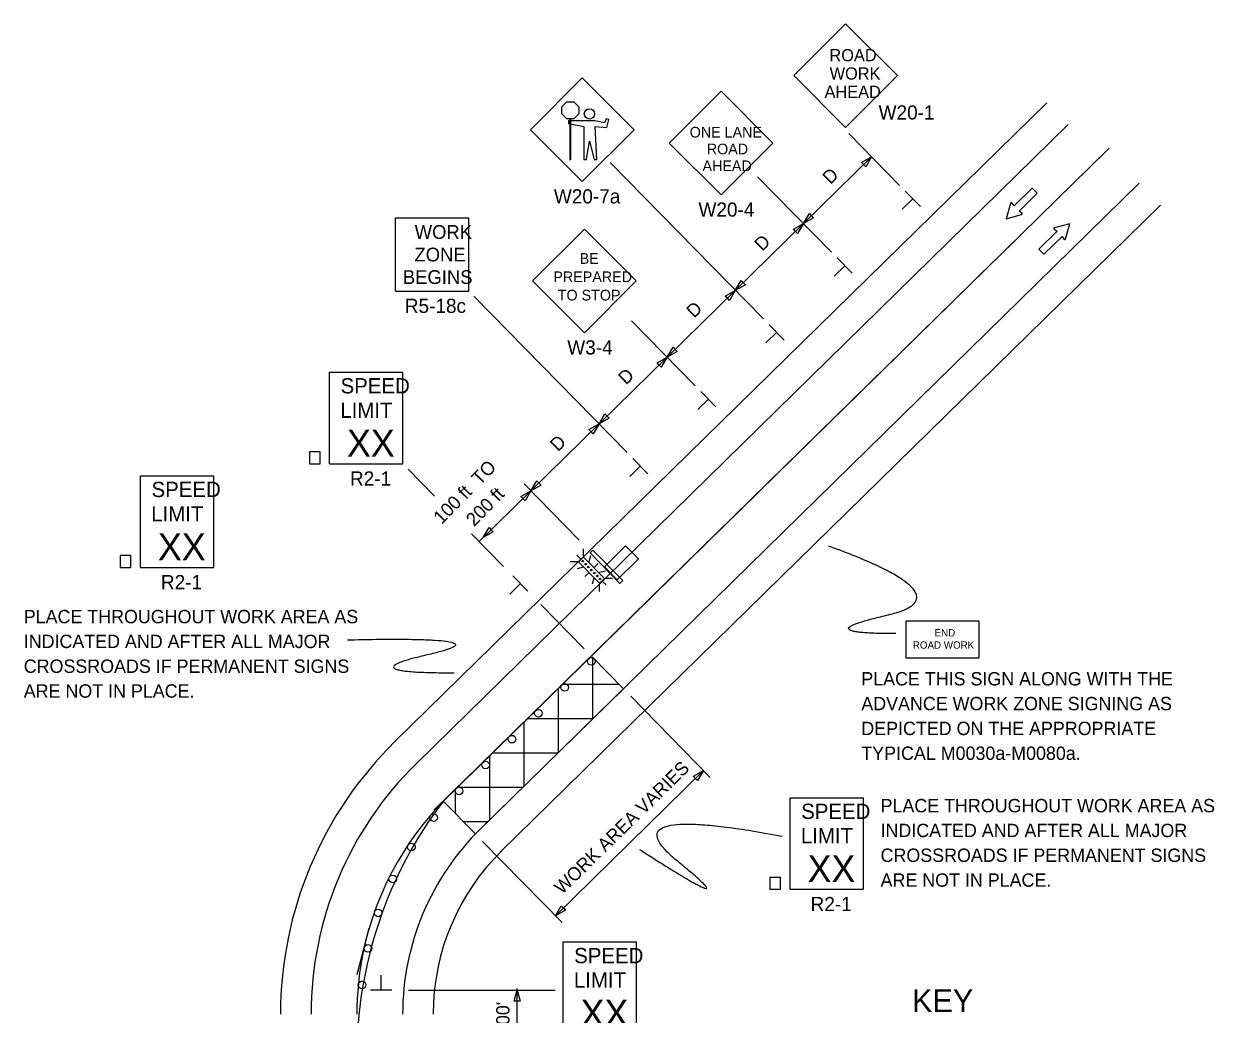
# Model space of a CAD drawing. Extents: x 16738 to 18485, y 7217 to 8213.
# Drawn here: x 16779 to 17403, y 7694 to 8213 of the extents above; entities that cross this region are included whole.
import ezdxf

# ---------------------------------------------------------------- set-up
doc = ezdxf.new("R2010")
doc.units = 0
for name, color, linetype in [('ALI_LEGAL_EX', 7, 'Continuous'), ('MT_SCRATCH_LEVEL_E', 7, 'Continuous'), ('PAVT_EDGE_EX', 7, 'Continuous'), ('TRAFFIC_SIGNS_PR', 7, 'Continuous'), ('TYPICAL_TEXT_DIMEN_EX', 7, 'Continuous'), ('TYPICAL_TEXT_DIMEN_PR', 7, 'Continuous')]:
    doc.layers.add(name, color=color, linetype=linetype)

msp = doc.modelspace()

# ---------------------------------------------------------------- linework, layer by layer
at = {"layer": 'ALI_LEGAL_EX'}
msp.add_line((16999.12, 7805.61), (17348.33, 8147.9), dxfattribs=at)
msp.add_arc((17174.73, 7671.79), 220.78, 142.68987, 180.19827, dxfattribs=at)
at = {"layer": 'MT_SCRATCH_LEVEL_E'}
for p, q in [((17307.86, 8126.93), (17298.39, 8117.65)), ((17307.86, 8126.93), (17298.39, 8117.65)), ((17301.01, 8114.98), (17310.48, 8124.26)), ((17301.01, 8114.98), (17310.48, 8124.26)), ((17310.48, 8124.26), (17307.86, 8126.93)), ((17310.48, 8124.26), (17307.86, 8126.93)), ((17296.55, 8119), (17294.28, 8110.97)), ((17296.55, 8119), (17294.28, 8110.97)), ((17298.39, 8117.65), (17297.37, 8119.14)), ((17298.39, 8117.65), (17297.37, 8119.14)), ((17294.28, 8110.97), (17302.33, 8113.11)), ((17294.28, 8110.97), (17302.33, 8113.11)), ((17302.48, 8113.93), (17301.01, 8114.98)), ((17302.48, 8113.93), (17301.01, 8114.98)), ((17320.93, 8104.35), (17311.46, 8095.07)), ((17320.93, 8104.35), (17311.46, 8095.07)), ((17319.46, 8105.4), (17320.93, 8104.35)), ((17319.46, 8105.4), (17320.93, 8104.35)), ((17327.66, 8108.35), (17319.61, 8106.22)), ((17327.66, 8108.35), (17319.61, 8106.22)), ((17325.39, 8100.32), (17327.66, 8108.35)), ((17325.39, 8100.32), (17327.66, 8108.35)), ((17314.08, 8092.4), (17323.55, 8101.68)), ((17314.08, 8092.4), (17323.55, 8101.68)), ((17323.55, 8101.68), (17324.56, 8100.19)), ((17323.55, 8101.68), (17324.56, 8100.19)), ((17311.46, 8095.07), (17314.08, 8092.4)), ((17311.46, 8095.07), (17314.08, 8092.4))]:
    msp.add_line(p, q, dxfattribs=at)
for centre, start, end in [((17296.99, 8118.87), 34.46189, 164.19881), ((17296.99, 8118.87), 34.46189, 164.19881), ((17302.2, 8113.55), 284.85054, 54.38951), ((17302.2, 8113.55), 284.85054, 54.38951), ((17319.73, 8105.77), 104.85054, 234.38951), ((17319.73, 8105.77), 104.85054, 234.38951), ((17324.94, 8100.46), 214.46189, 344.19881), ((17324.94, 8100.46), 214.46189, 344.19881)]:
    msp.add_arc(centre, 0.463, start, end, dxfattribs=at)
at = {"layer": 'PAVT_EDGE_EX'}
for p, q in [((16973.95, 7836.95), (17315.52, 8171.75)), ((17326.72, 8160.32), (16985.15, 7825.53)), ((17000.42, 7806.89), (17347.09, 8146.68)), ((17363.89, 8129.54), (17017.22, 7789.74)), ((17375.09, 8118.11), (17029.31, 7779.19)), ((17077.23, 7881.37), (17093.63, 7864.64)), ((17076.79, 7878.94), (17076.79, 7878.94))]:
    msp.add_line(p, q, dxfattribs=at)
for points in [[(17280.01, 8080.93), (17297.86, 8098.43)], [(17208.6, 8010.93), (17226.45, 8028.43)], [(17137.18, 7940.93), (17155.03, 7958.43)], [(17065.76, 7870.94), (17083.62, 7888.43)], [(16994.35, 7800.94), (17012.2, 7818.44)], [(16954.21, 7715), (16960.41, 7739.22)]]:
    msp.add_lwpolyline(points, dxfattribs=at)
for centre, radius, start, end in [((17113.95, 7694.12), 200, 134.42581, 180), ((17113.95, 7694.12), 184, 134.42582, 180), ((17113.95, 7694.12), 160, 134.35623, 180), ((17113.95, 7694.12), 136, 134.35623, 180), ((17113.95, 7694.12), 120, 134.35623, 180), ((17155.85, 7650.09), 180.78, 134.42580555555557, 134.42580833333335), ((17155.85, 7650.09), 180.78, 134.42580555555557, 134.42580833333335), ((17155.85, 7650.09), 180.78, 134.42580555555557, 134.42580833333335), ((17155.85, 7650.09), 180.78, 134.42580555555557, 134.42580833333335)]:
    msp.add_arc(centre, radius, start, end, dxfattribs=at)
at = {"layer": 'TRAFFIC_SIGNS_PR'}
for p, q in [((17210.11, 8213.07), (17182.96, 8185.92)), ((17237.26, 8185.92), (17210.11, 8213.07)), ((17182.96, 8185.92), (17210.11, 8158.77)), ((17210.11, 8158.77), (17237.26, 8185.92)), ((17072.08, 8184.69), (17044.93, 8157.54)), ((17099.23, 8157.54), (17072.08, 8184.69)), ((17144.83, 8177.77), (17117.67, 8150.61)), ((17171.98, 8150.61), (17144.83, 8177.77)), ((17044.93, 8157.54), (17072.08, 8130.39)), ((17072.08, 8130.39), (17099.23, 8157.54)), ((17117.67, 8150.61), (17144.83, 8123.46)), ((17144.83, 8123.46), (17171.98, 8150.61)), ((16974.29, 8073), (16974.29, 8111.4)), ((16974.29, 8111.4), (17012.69, 8111.4)), ((17012.69, 8073), (17012.69, 8111.4)), ((17073.24, 8105.53), (17046.09, 8078.38)), ((17100.39, 8078.38), (17073.24, 8105.53)), ((17046.09, 8078.38), (17073.24, 8051.23)), ((17073.24, 8051.23), (17100.39, 8078.38)), ((16974.29, 8073), (17012.69, 8073)), ((16939.67, 8030.54), (16978.07, 8030.54)), ((16939.67, 7982.54), (16939.67, 8030.54)), ((16978.07, 7982.54), (16978.07, 8030.54)), ((16939.67, 7982.54), (16978.07, 7982.54)), ((16840.6, 7976.23), (16879, 7976.23)), ((16840.6, 7928.23), (16840.6, 7976.23)), ((16879, 7928.23), (16879, 7976.23)), ((17072.73, 7934), (17072.77, 7937.99)), ((17083.69, 7928.6), (17094.84, 7939.52)), ((17101.55, 7932.68), (17094.84, 7939.52)), ((17069.82, 7931.16), (17065.83, 7931.2)), ((17071.28, 7932.58), (17069.3, 7934.59)), ((17072.32, 7931.51), (17072.32, 7931.51)), ((17073.84, 7929.96), (17073.84, 7929.96)), ((17076.35, 7934.33), (17075.47, 7931.2)), ((17078.39, 7928.23), (17080.4, 7930.2)), ((17090.41, 7921.75), (17101.55, 7932.68)), ((16840.6, 7928.23), (16879, 7928.23)), ((17072.59, 7928.34), (17069.44, 7927.52)), ((17075.48, 7925.38), (17073.47, 7923.41)), ((17075.36, 7928.41), (17075.36, 7928.41)), ((17076.88, 7926.86), (17076.88, 7926.86)), ((17078.4, 7925.3), (17078.4, 7925.3)), ((17079.93, 7923.75), (17079.93, 7923.75)), ((17084.23, 7926.3), (17081.08, 7925.48)), ((17078.15, 7922.66), (17077.28, 7919.52)), ((17081.1, 7915.62), (17081.14, 7919.61)), ((17081.45, 7922.2), (17081.45, 7922.2)), ((17082.59, 7921.03), (17084.57, 7919.02)), ((17088.03, 7922.41), (17084.05, 7922.45)), ((17181.08, 7807.56), (17219.48, 7807.56)), ((17181.08, 7759.56), (17181.08, 7807.56)), ((17219.48, 7759.56), (17219.48, 7807.56)), ((17181.08, 7759.56), (17219.48, 7759.56)), ((17062.1, 7731.95), (17100.5, 7731.95)), ((17062.1, 7683.95), (17062.1, 7731.95)), ((17100.5, 7683.95), (17100.5, 7731.95))]:
    msp.add_line(p, q, dxfattribs=at)
for points in [[(17064.04, 8172.17), (17067.71, 8172.17), (17070.31, 8169.57), (17070.31, 8165.9), (17067.71, 8163.3), (17064.04, 8163.3), (17061.44, 8165.9), (17061.44, 8169.57)], [(17078.76, 8162.26), (17064.94, 8162.26), (17064.94, 8160.76), (17072.9, 8159.31), (17072.9, 8141.9), (17074.4, 8141.9), (17075.9, 8151.51), (17078.3, 8141.9), (17079.8, 8141.9), (17078.9, 8159.31), (17084.9, 8158.7), (17086.1, 8162.9), (17084.65, 8163.27), (17083.75, 8161.17)], [(17065.58, 8163.3), (17065.58, 8141.92), (17066.17, 8141.92), (17066.17, 8163.3)], [(16929.06, 7982.54), (16934.65, 7982.54), (16934.65, 7988.71), (16929.06, 7988.71)], [(17076.17, 7935.8), (17091.84, 7919.82), (17093.34, 7921.29), (17077.67, 7937.27)], [(17090.41, 7921.75), (17083.69, 7928.6), (17094.84, 7939.52), (17101.55, 7932.68)], [(16829.99, 7928.23), (16835.58, 7928.23), (16835.58, 7934.41), (16829.99, 7934.41)], [(17072.72, 7933.67), (17083.72, 7922.46), (17081.15, 7919.94), (17070.15, 7931.15)], [(17241.75, 7880.91), (17280.15, 7880.91), (17280.15, 7900.11), (17241.75, 7900.11)], [(17170.47, 7759.56), (17176.06, 7759.56), (17176.06, 7765.73), (17170.47, 7765.73)]]:
    msp.add_lwpolyline(points, close=True, dxfattribs=at)
for centre, radius in [((17075.88, 8165.88), 2.7), ((17072.32, 7931.51), 0.379), ((17073.84, 7929.96), 0.379), ((17075.36, 7928.41), 0.379), ((17076.88, 7926.86), 0.379), ((17078.4, 7925.3), 0.379), ((17079.93, 7923.75), 0.379), ((17081.43, 7922.21), 0.379), ((17076.79, 7878.94), 2), ((17062.95, 7865.37), 2), ((17049.1, 7851.8), 2), ((17035.26, 7838.23), 2), ((17021.42, 7824.66), 2), ((17007.57, 7811.09), 2), ((16994.18, 7797.16), 2), ((16982.47, 7781.73), 2), ((16972.74, 7764.98), 2), ((16965.13, 7747.17), 2), ((16959.75, 7728.56), 2), ((16956.7, 7709.43), 2)]:
    msp.add_circle(centre, radius, dxfattribs=at)
for points in [[(17236.53, 7893.52), (17189.3, 7893.52), (17274.32, 7912.87), (17201.2, 7939.42)], [(16949.14, 7890.29), (17034.03, 7892.22), (16949.01, 7872.87), (17004.89, 7873.04)], [(17102.14, 7780.44), (17160.35, 7743.05), (17084.36, 7804.9), (17176.81, 7787.41)]]:
    msp.add_open_spline(points, degree=2, dxfattribs=at)
at = {"layer": 'TYPICAL_TEXT_DIMEN_PR'}
for p, q in [((17238.44, 8128.39), (17211.76, 8155.61)), ((17223.74, 8143.39), (17188.03, 8108.39)), ((17218.45, 8140.41), (17223.74, 8143.39)), ((17218.45, 8140.41), (17223.74, 8143.39)), ((17223.74, 8143.39), (17220.65, 8138.17)), ((17223.74, 8143.39), (17220.65, 8138.17)), ((17167.02, 8058.4), (17086.68, 8140.37)), ((17219.55, 8139.29), (17218.45, 8140.41)), ((17219.55, 8139.29), (17218.45, 8140.41)), ((17220.65, 8138.17), (17219.55, 8139.29)), ((17220.65, 8138.17), (17219.55, 8139.29)), ((17202.73, 8093.39), (17163.97, 8132.94)), ((17241.41, 8125.36), (17249.29, 8117.32)), ((17245.35, 8121.34), (17239.79, 8115.89)), ((17188.03, 8108.39), (17191.12, 8113.62)), ((17188.03, 8108.39), (17191.12, 8113.62)), ((17193.31, 8111.38), (17188.03, 8108.39)), ((17193.31, 8111.38), (17188.03, 8108.39)), ((17191.12, 8113.62), (17192.22, 8112.5)), ((17191.12, 8113.62), (17192.22, 8112.5)), ((17192.22, 8112.5), (17193.31, 8111.38)), ((17192.22, 8112.5), (17193.31, 8111.38)), ((17188.03, 8108.39), (17152.32, 8073.4)), ((17182.74, 8105.41), (17188.03, 8108.39)), ((17182.74, 8105.41), (17188.03, 8108.39)), ((17183.84, 8104.29), (17182.74, 8105.41)), ((17183.84, 8104.29), (17182.74, 8105.41)), ((17184.94, 8103.17), (17183.84, 8104.29)), ((17184.94, 8103.17), (17183.84, 8104.29)), ((17188.03, 8108.39), (17184.94, 8103.17)), ((17188.03, 8108.39), (17184.94, 8103.17)), ((17209.64, 8086.34), (17204.08, 8080.89)), ((17205.7, 8090.36), (17213.58, 8082.33)), ((17152.32, 8073.4), (17116.61, 8038.4)), ((17147.04, 8070.41), (17152.32, 8073.4)), ((17147.04, 8070.41), (17152.32, 8073.4)), ((17152.32, 8073.4), (17149.24, 8068.17)), ((17152.32, 8073.4), (17149.24, 8068.17)), ((17152.32, 8073.4), (17155.41, 8078.62)), ((17157.61, 8076.38), (17152.32, 8073.4)), ((17155.41, 8078.62), (17156.51, 8077.5)), ((17156.51, 8077.5), (17157.61, 8076.38)), ((17095.61, 7988.39), (17015.31, 8070.33)), ((17148.14, 8069.29), (17147.04, 8070.41)), ((17148.14, 8069.29), (17147.04, 8070.41)), ((17149.24, 8068.17), (17148.14, 8069.29)), ((17149.24, 8068.17), (17148.14, 8069.29)), ((17131.32, 8023.39), (17097.95, 8057.44)), ((17170, 8055.36), (17177.87, 8047.33)), ((17173.93, 8051.35), (17168.37, 8045.9)), ((17116.61, 8038.4), (17119.7, 8043.62)), ((17116.61, 8038.4), (17119.7, 8043.62)), ((17119.7, 8043.62), (17120.8, 8042.5)), ((17119.7, 8043.62), (17120.8, 8042.5)), ((17120.8, 8042.5), (17121.9, 8041.38)), ((17120.8, 8042.5), (17121.9, 8041.38)), ((17116.62, 8038.39), (17080.91, 8003.39)), ((17111.33, 8035.41), (17116.62, 8038.39)), ((17111.33, 8035.41), (17116.62, 8038.39)), ((17116.62, 8038.39), (17113.53, 8033.17)), ((17116.62, 8038.39), (17113.53, 8033.17)), ((17121.9, 8041.38), (17116.61, 8038.4)), ((17121.9, 8041.38), (17116.61, 8038.4)), ((17112.43, 8034.29), (17111.33, 8035.41)), ((17112.43, 8034.29), (17111.33, 8035.41)), ((17113.53, 8033.17), (17112.43, 8034.29)), ((17113.53, 8033.17), (17112.43, 8034.29)), ((17134.29, 8020.36), (17142.16, 8012.33)), ((17138.23, 8016.35), (17132.67, 8010.9)), ((17080.91, 8003.4), (17083.99, 8008.62)), ((17080.91, 8003.4), (17083.99, 8008.62)), ((17086.19, 8006.38), (17080.91, 8003.4)), ((17086.19, 8006.38), (17080.91, 8003.4)), ((17083.99, 8008.62), (17085.09, 8007.5)), ((17083.99, 8008.62), (17085.09, 8007.5)), ((17085.09, 8007.5), (17086.19, 8006.38)), ((17085.09, 8007.5), (17086.19, 8006.38)), ((17080.91, 8003.39), (17045.2, 7968.4)), ((17075.62, 8000.41), (17080.91, 8003.39)), ((17075.62, 8000.41), (17080.91, 8003.39)), ((17076.72, 7999.29), (17075.62, 8000.41)), ((17076.72, 7999.29), (17075.62, 8000.41)), ((17077.82, 7998.17), (17076.72, 7999.29)), ((17077.82, 7998.17), (17076.72, 7999.29)), ((17080.91, 8003.39), (17077.82, 7998.17)), ((17080.91, 8003.39), (17077.82, 7998.17)), ((16994.69, 7965.59), (16980.86, 7979.7)), ((17102.52, 7981.35), (17096.96, 7975.9)), ((17098.58, 7985.36), (17106.46, 7977.33)), ((17045.2, 7968.4), (17048.28, 7973.62)), ((17045.2, 7968.4), (17048.28, 7973.62)), ((17048.28, 7973.62), (17049.39, 7972.5)), ((17048.28, 7973.62), (17049.39, 7972.5)), ((17045.2, 7968.4), (17018.03, 7941.77)), ((17039.91, 7965.41), (17045.2, 7968.4)), ((17039.91, 7965.41), (17045.2, 7968.4)), ((17070.49, 7942.59), (17041.7, 7971.97)), ((17045.2, 7968.4), (17042.11, 7963.17)), ((17045.2, 7968.4), (17042.11, 7963.17)), ((17050.48, 7971.38), (17045.2, 7968.4)), ((17050.48, 7971.38), (17045.2, 7968.4)), ((17049.39, 7972.5), (17050.48, 7971.38)), ((17049.39, 7972.5), (17050.48, 7971.38)), ((17041.01, 7964.29), (17039.91, 7965.41)), ((17041.01, 7964.29), (17039.91, 7965.41)), ((17042.11, 7963.17), (17041.01, 7964.29)), ((17042.11, 7963.17), (17041.01, 7964.29)), ((17020.2, 7943.9), (17023.29, 7949.12)), ((17023.29, 7949.12), (17024.39, 7948)), ((17030.81, 7928.74), (17014.1, 7945.78)), ((17025.49, 7946.88), (17020.2, 7943.9)), ((17024.39, 7948), (17025.49, 7946.88)), ((17035.73, 7923.76), (17043.6, 7915.73)), ((17039.67, 7919.74), (17034.11, 7914.29)), ((17073.14, 7885.54), (17050.39, 7908.75)), ((17077.61, 7848.94), (17077.61, 7880.98)), ((17018.87, 7791.36), (17093.63, 7864.64)), ((17059.61, 7831.29), (17059.61, 7864.9)), ((17091.42, 7866.89), (17061.64, 7866.89)), ((17139.13, 7818.22), (17097.51, 7860.68)), ((17077.56, 7848.89), (17043.28, 7848.89)), ((17041.61, 7813.65), (17041.61, 7847.26)), ((17059.2, 7830.89), (17024.91, 7830.89)), ((17023.61, 7796.01), (17023.61, 7829.61)), ((17135.63, 7821.79), (17058.02, 7745.73)), ((17130.34, 7818.81), (17135.63, 7821.79)), ((17131.44, 7817.69), (17130.34, 7818.81)), ((17132.54, 7816.57), (17131.44, 7817.69)), ((17135.63, 7821.79), (17132.54, 7816.57)), ((17005.61, 7799.2), (17005.61, 7811.97)), ((17040.83, 7812.89), (17006.55, 7812.89)), ((17016.06, 7788.54), (16999.26, 7805.68)), ((16999.26, 7805.68), (17016.06, 7788.54)), ((17022.47, 7794.89), (17009.84, 7794.89)), ((17061.52, 7742.16), (17019.9, 7784.62)), ((17058.02, 7745.73), (17061.11, 7750.95)), ((17063.31, 7748.71), (17058.02, 7745.73)), ((17061.11, 7750.95), (17062.21, 7749.83)), ((17062.21, 7749.83), (17063.31, 7748.71)), ((16966.72, 7706.77), (16966.72, 7714.55)), ((16972.35, 7706.77), (16961.1, 7706.77)), ((16981.01, 7706.78), (17057.95, 7706.78)), ((17036.38, 7700.92), (17037.95, 7706.78)), ((17036.38, 7700.92), (17037.95, 7706.78)), ((17037.95, 7672.69), (17037.95, 7707.54)), ((17037.95, 7706.78), (17039.52, 7700.92)), ((17037.95, 7706.78), (17039.52, 7700.92)), ((17037.95, 7700.92), (17036.38, 7700.92)), ((17037.95, 7700.92), (17036.38, 7700.92)), ((17039.52, 7700.92), (17037.95, 7700.92)), ((17039.52, 7700.92), (17037.95, 7700.92))]:
    msp.add_line(p, q, dxfattribs=at)
msp.add_arc((17113.95, 7694.12), 136, 134.35623, 136.03218, dxfattribs=at)

# ---------------------------------------------------------------- texts
at = {"layer": 'TRAFFIC_SIGNS_PR'}
for s, height, p in [('ROAD', 6.4, (17201.65, 8193.45)), ('WORK', 6.4, (17201.76, 8183.86)), ('AHEAD', 6.4, (17199.07, 8174.26)), ('W20-1', 7.44, (17227.42, 8162.91)), ('ONE LANE', 5.6, (17128.41, 8153.48)), ('ROAD', 5.6, (17137.36, 8144.68)), ('AHEAD', 5.6, (17135.12, 8135.88)), ('W20-7a', 7.44, (17057.22, 8118.95)), ('W20-4', 7.44, (17133.01, 8112.02)), ('WORK', 7.217, (16984.29, 8100.37)), ('ZONE', 7.217, (16984.17, 8088.56)), ('BE', 5.6, (17070.74, 8087.3)), ('BEGINS', 7.217, (16978.1, 8076.75)), ('PREPARED', 5.6, (17056.98, 8077.7)), ('TO STOP', 5.6, (17059.27, 8068.1)), ('R5-18c', 7.44, (16979.1, 8061.56)), ('W3-4', 7.44, (17064.25, 8039.79)), ('SPEED', 8, (16945.44, 8019.4)), ('LIMIT', 8, (16945.28, 8006.6)), ('XX', 14.031, (16948.78, 7986.3)), ('R2-1', 7.44, (16950.35, 7971.1)), ('SPEED', 8, (16846.36, 7965.1)), ('LIMIT', 8, (16846.2, 7952.3)), ('XX', 14.031, (16849.71, 7931.99)), ('R2-1', 7.44, (16851.27, 7916.79)), ('PLACE THROUGHOUT WORK AREA AS', 7, (16779.39, 7898.97)), ('INDICATED AND AFTER ALL MAJOR', 7, (16779.39, 7885.97)), ('END', 3.831, (17256.75, 7892.04)), ('ROAD WORK', 3.831, (17245.36, 7885.65)), ('CROSSROADS IF PERMANENT SIGNS', 7, (16779.39, 7872.97)), ('PLACE THIS SIGN ALONG WITH THE', 7, (17218.36, 7866.37)), ('ARE NOT IN PLACE.', 7, (16779.39, 7859.97)), ('ADVANCE WORK ZONE SIGNING AS', 7, (17218.36, 7853.37)), ('DEPICTED ON THE APPROPRIATE', 7, (17218.36, 7840.37)), ('TYPICAL M0030a-M0080a.', 7, (17218.36, 7827.37)), ('PLACE THROUGHOUT WORK AREA AS', 7, (17228.45, 7799.9)), ('SPEED', 8, (17186.84, 7796.42)), ('INDICATED AND AFTER ALL MAJOR', 7, (17228.45, 7786.9)), ('LIMIT', 8, (17186.68, 7783.62)), ('CROSSROADS IF PERMANENT SIGNS', 7, (17228.45, 7773.9)), ('XX', 14.031, (17190.19, 7763.32)), ('ARE NOT IN PLACE.', 7, (17228.45, 7760.9)), ('R2-1', 7.44, (17191.75, 7748.12)), ('SPEED', 8, (17067.86, 7720.81)), ('LIMIT', 8, (17067.7, 7708.01)), ('XX', 14.031, (17071.21, 7687.7))]:
    msp.add_text(s, height=height, dxfattribs=at).set_placement(p)
at = {"layer": 'TYPICAL_TEXT_DIMEN_EX'}
msp.add_text('KEY', height=12, dxfattribs=at).set_placement((17244.92, 7695.19))
at = {"layer": 'TYPICAL_TEXT_DIMEN_PR'}
for s, rotation, p in [('D', 44.43273, (17202.17, 8128.54)), ('D', 44.43273, (17166.46, 8093.53)), ('D', 44.43273, (17130.76, 8058.53)), ('D', 44.43273, (17095.06, 8023.53)), ('D', 44.43273, (17059.35, 7988.53)), ('100 ft  TO', 45.6, (16998.39, 7950.48)), ('200 ft', 45.6, (17015.44, 7949.3)), ('WORK AREA VARIES', 44.42594, (17061.55, 7756.52)), ("100'", 90, (17033.98, 7683.2))]:
    msp.add_text(s, height=7, rotation=rotation, dxfattribs=at).set_placement(p)

doc.saveas('drawing.dxf')
